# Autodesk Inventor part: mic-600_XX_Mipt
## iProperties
Shininess: 20.0
Length Units: 11269
Angle Units: 11279
Time Units: 11290
Mass Units: 11283
Length Display Precision: 2
Angle Display Precision: 2
Part Number: mic-600_XX_Mipt
Material: Nichtrostender Stahl - 440C
Document SubType Name: Modellieren
Description: mic 600 Sensoren
Checked By: Alves
Created: 2005-08
Designer: Ohle
Manufacturer: Standard
Standards Organization: Custom
Density: 0.0
Volumn: 0.0
Area: 0.0
PropertySet Name: Model Information
Control State: 0
Master: False
Checked Out: False
Last Check In By: Kramp
Last Check In Date: 2005-08-09
BESTELLNUMMER: mic-600/XX/M
ME: ST
Title: mic Sensoren
Author: Ohle
Comments: keine Bemerkung
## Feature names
1. Grundkörper [Revolution]
2. Messkopf mic-600 [Revolution]
3. Bohrung1 [Hole]
4. Pole [Extrusion]
5. Abrundung Pole [Fillet]
6. Verdrehsicherung [Extrusion]
